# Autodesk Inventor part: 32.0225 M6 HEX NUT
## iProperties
Created: 2012-10
Part Number: 32.0225 M6 HEX NUT
Document SubType Name: Modeling
Designer: Administrator
Density: 7.85 g/cm^3
Material: Steel
Mass: 3.0149 g
Surface Area: 4.05042 cm^2
Volume: 0.384064 cm^3
Author: Administrator
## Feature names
1. Base1
2. Hole1
